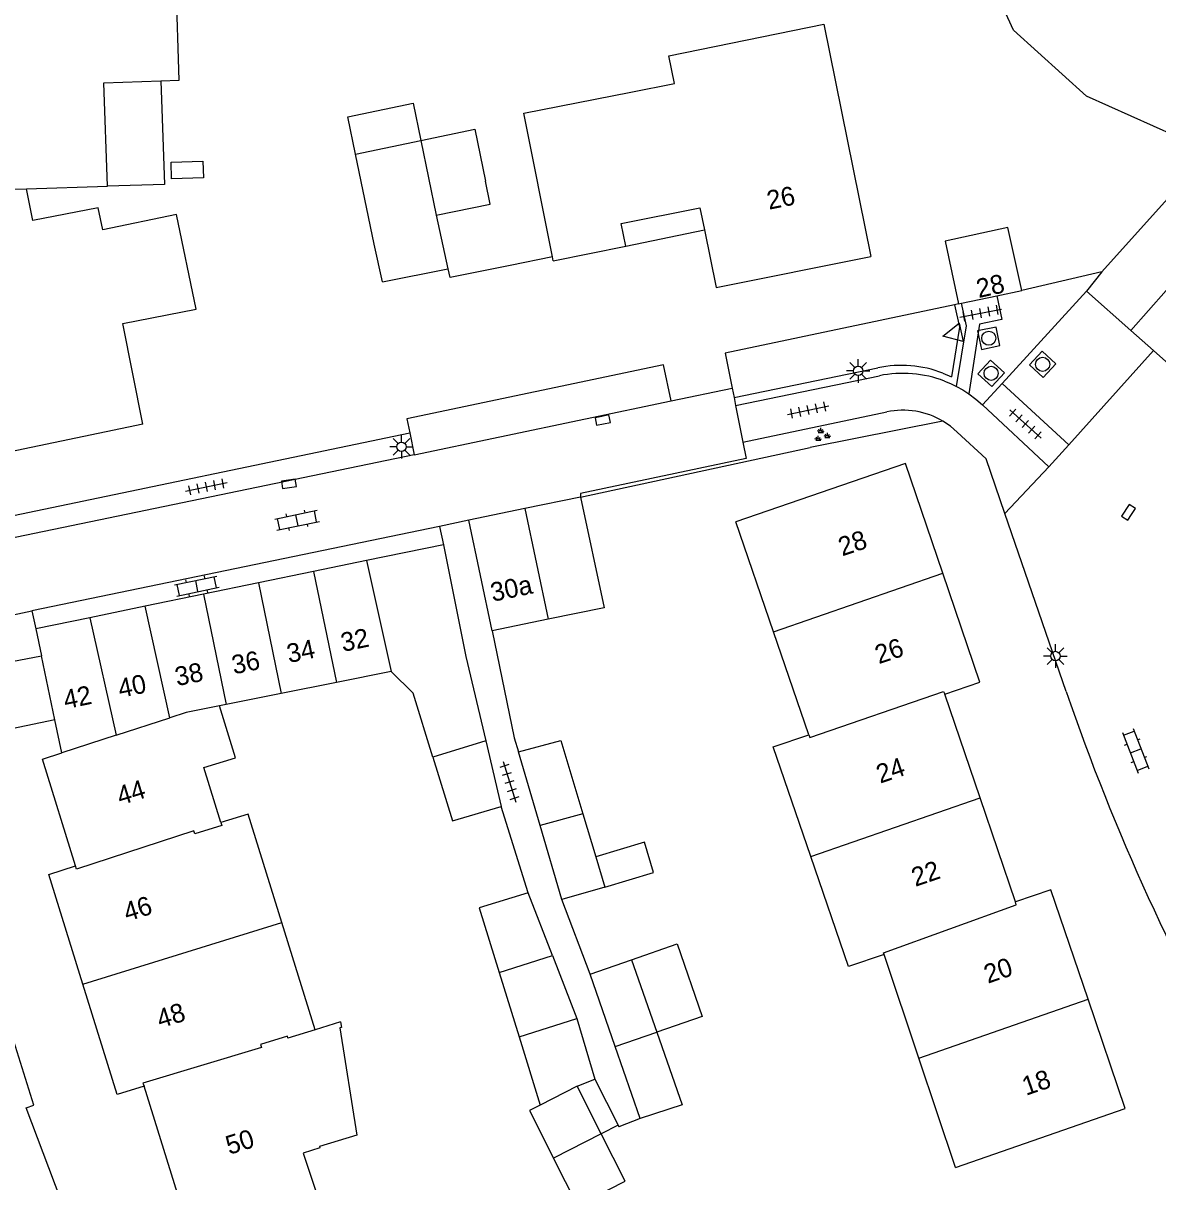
# Model space of a CAD drawing. Extents: x 126000 to 131009, y 393000 to 395500.
# Drawn here: x 130394.9 to 130455.1, y 394946.8 to 395008.4 of the extents above; entities that cross this region are included whole.
import ezdxf

# ---------------------------------------------------------------- set-up
doc = ezdxf.new("R2010")
doc.units = 0
for name, color, linetype in [('gg-afsc-erfafscheiding', 7, 'Continuous'), ('gg-afsc-muur', 7, 'Continuous'), ('gg-anno-huisnummerreeks BGT', 7, 'Continuous'), ('gg-bbg-bijgebouw', 7, 'Continuous'), ('gg-bbg-gedigitaliseerde bebouwing', 7, 'Continuous'), ('gg-bbg-gedigitaliseerde bijgebouw', 7, 'Continuous'), ('gg-bbg-hoofdgebouw', 7, 'Continuous'), ('gg-bbg-luifel en loopbrug', 7, 'Continuous'), ('gg-bbg-tussenscheiding', 7, 'Continuous'), ('gg-knt-verharding', 7, 'Continuous'), ('gg-knt-verharding nz', 7, 'Continuous'), ('gg-kntw-beschoeiing', 7, 'Continuous'), ('gt-grn-groengrens', 7, 'Continuous'), ('gt-symb-groenvak', 7, 'Continuous'), ('gt-symb-klinker verharding', 7, 'Continuous'), ('gt-symb-kolk', 7, 'Continuous'), ('gt-symb-lichtmast', 7, 'Continuous'), ('gt-symb-rioolschacht', 7, 'Continuous'), ('gt-symb-tegel verharding', 7, 'Continuous'), ('gt-symb-waterafsluiter', 7, 'Continuous')]:
    doc.layers.add(name, color=color, linetype=linetype)

# ---------------------------------------------------------------- blocks, each defined once
blk = doc.blocks.new('gt0-KL1')
at = {"layer": 'gt-symb-klinker verharding'}
for p, q in [((-1.15, 0.3), (1.15, 0.3)), ((-1, -0.3), (-1, 0.3)), ((-0.5, 0.3), (-0.5, 0.45)), ((0, -0.3), (0, 0.3)), ((0.5, 0.3), (0.5, 0.45)), ((1, -0.3), (1, 0.3)), ((-1.15, -0.3), (1.15, -0.3)), ((-0.5, -0.45), (-0.5, -0.3)), ((0.5, -0.45), (0.5, -0.3))]:
    blk.add_line(p, q, dxfattribs=at)
blk = doc.blocks.new('gt0-TEG1')
at = {"layer": 'gt-symb-tegel verharding'}
for p, q in [((-1.125, 0), (1.125, 0)), ((-0.9, -0.25), (-0.9, 0.25)), ((-0.45, -0.25), (-0.45, 0.25)), ((0, -0.25), (0, 0.25)), ((0.45, -0.25), (0.45, 0.25)), ((0.9, -0.25), (0.9, 0.25))]:
    blk.add_line(p, q, dxfattribs=at)
blk = doc.blocks.new('gt0-GRVAK')
at = {"layer": 'gt-symb-groenvak'}
for p, q in [((-0.11, 0.189), (-0.228, 0.24)), ((-0.182, 0.153), (0.088, 0.153)), ((-0.091, 0.211), (-0.156, 0.322)), ((-0.047, 0.214), (-0.047, 0.393)), ((-0.004, 0.211), (0.061, 0.322)), ((0.015, 0.189), (0.133, 0.24)), ((0.262, -0.052), (0.197, 0.059)), ((0.305, -0.049), (0.305, 0.13)), ((0.349, -0.052), (0.414, 0.059)), ((-0.245, -0.228), (-0.363, -0.177)), ((-0.318, -0.264), (-0.047, -0.264)), ((-0.226, -0.206), (-0.291, -0.095)), ((-0.183, -0.203), (-0.183, -0.024)), ((-0.139, -0.206), (-0.074, -0.095)), ((-0.12, -0.228), (-0.002, -0.177)), ((0.243, -0.074), (0.125, -0.023)), ((0.17, -0.11), (0.441, -0.11)), ((0.368, -0.074), (0.486, -0.023))]:
    blk.add_line(p, q, dxfattribs=at)
blk = doc.blocks.new('gt0-KOLK')
at = {"layer": 'gt-symb-kolk'}
blk.add_lwpolyline([(0, 0), (0.375, 0), (0.375, 0.4), (-0.375, 0.4), (-0.375, 0), (0, 0)], dxfattribs=at)
blk = doc.blocks.new('gt0-RS')
at = {"layer": 'gt-symb-rioolschacht'}
blk.add_lwpolyline([(-0.5, -0.5), (0.5, -0.5), (0.5, 0.5), (-0.5, 0.5)], close=True, dxfattribs=at)
blk.add_circle((0, 0), 0.375, dxfattribs=at)
blk = doc.blocks.new('gt0-LMAST')
at = {"layer": 'gt-symb-lichtmast'}
for p, q in [((-0.005, 0.246), (-0.005, 0.621)), ((-0.182, 0.173), (-0.447, 0.438)), ((0.172, 0.173), (0.437, 0.438)), ((-0.255, -0.004), (-0.63, -0.004)), ((-0.182, -0.181), (-0.447, -0.446)), ((-0.005, -0.254), (-0.005, -0.629)), ((0.437, -0.446), (0.172, -0.181)), ((0.245, -0.004), (0.62, -0.004))]:
    blk.add_line(p, q, dxfattribs=at)
blk.add_circle((-0.005, -0.004), 0.25, dxfattribs=at)
blk = doc.blocks.new('gt0-WAFSL')
at = {"layer": 'gt-symb-waterafsluiter'}
for p, q in [((-0.5, -0.333), (0, 0.667)), ((0, 0.667), (0.5, -0.333)), ((0.5, -0.333), (-0.5, -0.333))]:
    blk.add_line(p, q, dxfattribs=at)

msp = doc.modelspace()

# ---------------------------------------------------------------- linework, layer by layer
at = {"layer": 'gg-afsc-erfafscheiding'}
for p, q in [((130422.965, 394995.976), (130420.721, 394995.525)), ((130424.46, 394983.224), (130436.661, 394985.85)), ((130416.969, 394981.665), (130417.172, 394980.691)), ((130421.68, 394962.2), (130420.25, 394966.79)), ((130424.97, 394957.88), (130423.47, 394961.84)), ((130427.63, 394950.2), (130426.495, 394949.763)), ((130426.448, 394949.856), (130426.495, 394949.763))]:
    msp.add_line(p, q, dxfattribs=at)
msp.add_lwpolyline([(130419.77, 394976.122), (130420.94, 394970.437), (130421.16, 394969.69)], dxfattribs=at)
at = {"layer": 'gg-afsc-muur'}
msp.add_lwpolyline([(130420.721, 394995.525), (130417.525, 394994.883), (130417.43, 394995.353), (130417.401, 394995.347)], dxfattribs=at)
at = {"layer": 'gg-bbg-bijgebouw'}
for p, q in [((130413.943, 394994.646), (130417.401, 394995.347)), ((130424.46, 394983.224), (130421.495, 394982.607)), ((130417.172, 394980.691), (130413.088, 394979.847)), ((130413.088, 394979.847), (130410.282, 394979.267)), ((130410.282, 394979.267), (130407.358, 394978.663)), ((130407.358, 394978.663), (130404.434, 394978.059)), ((130404.434, 394978.059), (130401.327, 394977.417)), ((130401.327, 394977.417), (130398.389, 394976.81)), ((130398.389, 394976.81), (130395.527, 394976.219)), ((130395.527, 394976.219), (130395.824, 394974.794)), ((130396.535, 394971.381), (130395.824, 394974.794)), ((130396.9, 394969.632), (130396.535, 394971.381))]:
    msp.add_line(p, q, dxfattribs=at)
at = {"layer": 'gg-bbg-gedigitaliseerde bebouwing'}
for p, q in [((130437.38, 395008.35), (130439.874, 394996.006)), ((130395.04, 394999.6), (130399.33, 394999.73)), ((130401.218, 394987.088), (130400.15, 394992.44)), ((130419.77, 394976.122), (130418.53, 394981.989)), ((130434.712, 394976.054), (130432.711, 394981.906)), ((130422.745, 394976.731), (130419.77, 394976.122)), ((130436.58, 394970.59), (130434.712, 394976.054)), ((130410.357, 394954.927), (130408.586, 394960.627)), ((130442.428, 394953.419), (130440.58, 394958.92)), ((130411.713, 394955.349), (130410.357, 394954.927)), ((130444.38, 394947.61), (130442.428, 394953.419)), ((130444.38, 394947.61), (130453.389, 394950.744))]:
    msp.add_line(p, q, dxfattribs=at)
for points in [[(130402.168, 395005.326), (130403.14, 395005.36), (130402.98, 395010.45), (130402.382, 395010.428)], [(130421.437, 395003.614), (130427.13, 395004.723), (130429.45, 395005.19), (130429.15, 395006.66), (130437.38, 395008.35)], [(130399.33, 394999.73), (130399.14, 395005.22), (130402.168, 395005.326)], [(130400.15, 394992.44), (130404.04, 394993.21), (130403, 394998.23), (130399.08, 394997.41), (130398.83, 394998.59), (130395.37, 394997.92), (130395.04, 394999.6)], [(130405.351, 394965.935), (130404.45, 394968.854), (130406.132, 394969.374), (130405.28, 394972.134)], [(130436.683, 394964.121), (130434.69, 394969.95), (130436.58, 394970.59)], [(130408.586, 394960.627), (130406.798, 394966.384), (130405.351, 394965.935)], [(130440.58, 394958.92), (130438.68, 394958.28), (130436.683, 394964.121)]]:
    msp.add_lwpolyline(points, dxfattribs=at)
at = {"layer": 'gg-bbg-gedigitaliseerde bijgebouw'}
for p, q in [((130416.798, 394998.197), (130417.401, 394995.347)), ((130417.172, 394980.691), (130418.361, 394974.753)), ((130418.361, 394974.753), (130419.425, 394970.269)), ((130414.4, 394973.96), (130411.492, 394973.378)), ((130408.561, 394972.791), (130405.633, 394972.205)), ((130411.492, 394973.378), (130408.561, 394972.791)), ((130405.633, 394972.205), (130405.28, 394972.134)), ((130419.425, 394970.269), (130420.25, 394966.79)), ((130422.314, 394965.768), (130421.16, 394969.69)), ((130424.579, 394966.4), (130425.266, 394964.111)), ((130423.47, 394961.84), (130422.314, 394965.768)), ((130425.266, 394964.111), (130425.75, 394962.5)), ((130425.75, 394962.5), (130423.47, 394961.84)), ((130422.97, 394958.86), (130421.68, 394962.2)), ((130422.97, 394958.86), (130424.26, 394955.52)), ((130424.97, 394957.88), (130427.16, 394958.64)), ((130427.16, 394958.64), (130428.504, 394954.793)), ((130420.135, 394957.969), (130421.19, 394954.54)), ((130426.301, 394954.038), (130424.97, 394957.88)), ((130421.19, 394954.54), (130424.26, 394955.52)), ((130427.63, 394950.2), (130426.301, 394954.038)), ((130424.28, 394951.92), (130422.305, 394950.917)), ((130425.554, 394949.401), (130424.28, 394951.92)), ((130424.3, 394945.59), (130423.02, 394948.11))]:
    msp.add_line(p, q, dxfattribs=at)
for points in [[(130412.51, 395001.44), (130412.098, 395003.427), (130415.573, 395004.148), (130415.98, 395002.17)], [(130415.98, 395002.17), (130418.847, 395002.76), (130419.415, 395000)], [(130413.943, 394994.646), (130413.503, 394996.656), (130412.51, 395001.44)], [(130416.798, 394998.197), (130419.665, 394998.787), (130419.415, 395000)], [(130424.46, 394983.224), (130425.72, 394977.34), (130422.745, 394976.731)], [(130416.612, 394969.41), (130415.56, 394972.8), (130414.4, 394973.96)], [(130421.16, 394969.69), (130423.41, 394970.29), (130424.579, 394966.4)], [(130416.612, 394969.41), (130417.66, 394966.03), (130420.25, 394966.79)], [(130421.68, 394962.2), (130419.08, 394961.4), (130420.135, 394957.969)], [(130428.504, 394954.793), (130429.85, 394950.94), (130427.63, 394950.2)], [(130422.305, 394950.917), (130421.74, 394950.63), (130423.02, 394948.11)], [(130424.3, 394945.59), (130426.83, 394946.88), (130425.554, 394949.401)]]:
    msp.add_lwpolyline(points, dxfattribs=at)
at = {"layer": 'gg-bbg-hoofdgebouw'}
for p, q in [((130422.965, 394995.976), (130421.437, 395003.614)), ((130423.005, 394995.777), (130426.858, 394996.552)), ((130423.005, 394995.777), (130422.965, 394995.976)), ((130444.695, 394993.514), (130446.562, 394993.909)), ((130446.562, 394993.909), (130447.891, 394994.19)), ((130444.524, 394993.478), (130444.695, 394993.514)), ((130421.495, 394982.607), (130418.53, 394981.989)), ((130445.675, 394967.235), (130443.796, 394972.748)), ((130447.555, 394961.716), (130445.675, 394967.235)), ((130453.389, 394950.744), (130451.41, 394956.554))]:
    msp.add_line(p, q, dxfattribs=at)
for points in [[(130426.858, 394996.552), (130426.615, 394997.76), (130430.795, 394998.593), (130431.036, 394997.416)], [(130431.036, 394997.416), (130431.666, 394994.347), (130439.874, 394996.006)], [(130447.891, 394994.19), (130447.142, 394997.548), (130443.82, 394996.807), (130444.524, 394993.478)], [(130401.218, 394987.088), (130393.315, 394985.453), (130392.237, 394990.549), (130390.919, 394990.27)], [(130443.697, 394979.186), (130441.724, 394984.999), (130432.711, 394981.906)], [(130443.796, 394972.748), (130445.667, 394973.383), (130443.697, 394979.186)], [(130397.632, 394963.627), (130395.88, 394969.304), (130396.9, 394969.632)], [(130398.031, 394957.336), (130396.216, 394963.178), (130397.632, 394963.627)], [(130451.41, 394956.554), (130449.436, 394962.351), (130447.555, 394961.716)], [(130401.273, 394951.933), (130399.847, 394951.49), (130398.031, 394957.336)], [(130411.713, 394955.349), (130411.758, 394955.035), (130411.677, 394955.019), (130412.57, 394949.322), (130410.6, 394948.716), (130410.619, 394948.654), (130409.724, 394948.365), (130410.436, 394946.239), (130403.063, 394943.186)], [(130402.157, 394945.922), (130403.056, 394946.227), (130401.273, 394951.933)]]:
    msp.add_lwpolyline(points, dxfattribs=at)
at = {"layer": 'gg-bbg-luifel en loopbrug'}
for p, q in [((130426.858, 394996.552), (130431.036, 394997.416)), ((130424.26, 394955.52), (130425.21, 394952.303)), ((130421.19, 394954.54), (130422.305, 394950.917)), ((130424.28, 394951.92), (130425.21, 394952.303)), ((130425.21, 394952.303), (130426.448, 394949.856)), ((130426.448, 394949.856), (130425.554, 394949.401))]:
    msp.add_line(p, q, dxfattribs=at)
for points in [[(130402.168, 395005.326), (130402.359, 394999.818), (130399.33, 394999.73)], [(130402.74, 395000.118), (130402.709, 395001.014), (130404.396, 395001.073), (130404.427, 395000.176), (130402.74, 395000.118)], [(130425.75, 394962.5), (130428.339, 394963.277), (130427.856, 394964.888), (130425.266, 394964.111)], [(130427.16, 394958.64), (130429.582, 394959.48), (130430.921, 394955.621), (130428.504, 394954.793)]]:
    msp.add_lwpolyline(points, dxfattribs=at)
at = {"layer": 'gg-bbg-tussenscheiding'}
for p, q in [((130412.51, 395001.44), (130415.98, 395002.17)), ((130415.98, 395002.17), (130416.798, 394998.197)), ((130392.042, 394999.511), (130395.04, 394999.6)), ((130421.495, 394982.607), (130422.745, 394976.731)), ((130413.088, 394979.847), (130414.4, 394973.96)), ((130410.282, 394979.267), (130411.492, 394973.378)), ((130434.712, 394976.054), (130443.697, 394979.186)), ((130407.358, 394978.663), (130408.561, 394972.791)), ((130404.434, 394978.059), (130405.633, 394972.205)), ((130402.65, 394971.5), (130401.327, 394977.417)), ((130398.389, 394976.81), (130399.79, 394970.57)), ((130399.79, 394970.57), (130402.65, 394971.5)), ((130399.79, 394970.57), (130396.9, 394969.632)), ((130419.425, 394970.269), (130416.612, 394969.41)), ((130436.683, 394964.121), (130445.675, 394967.235)), ((130424.579, 394966.4), (130422.314, 394965.768)), ((130398.031, 394957.336), (130408.586, 394960.627)), ((130420.135, 394957.969), (130422.97, 394958.86)), ((130442.428, 394953.419), (130451.41, 394956.554)), ((130426.301, 394954.038), (130428.504, 394954.793)), ((130425.554, 394949.401), (130423.02, 394948.11))]:
    msp.add_line(p, q, dxfattribs=at)
for points in [[(130436.58, 394970.59), (130436.64, 394970.44), (130443.73, 394972.89), (130443.796, 394972.748)], [(130405.28, 394972.134), (130403.51, 394971.78), (130402.65, 394971.5)], [(130405.351, 394965.935), (130405.4, 394965.78), (130403.97, 394965.33), (130403.92, 394965.49), (130397.69, 394963.46), (130397.632, 394963.627)], [(130440.58, 394958.92), (130440.54, 394959.01), (130447.6, 394961.56), (130447.555, 394961.716)], [(130410.357, 394954.927), (130408.92, 394954.48), (130408.89, 394954.58), (130407.46, 394954.14), (130407.51, 394953.98), (130401.21, 394952.08), (130401.273, 394951.933)]]:
    msp.add_lwpolyline(points, dxfattribs=at)
at = {"layer": 'gg-knt-verharding'}
for p, q in [((130446.854, 394989.252), (130451.32, 394994.155)), ((130451.32, 394994.155), (130453.677, 394992.067)), ((130453.677, 394992.067), (130454.882, 394991)), ((130454.882, 394991), (130457.015, 394989.111)), ((130432.692, 394988.094), (130440.331, 394989.666)), ((130429.271, 394988.329), (130432.511, 394989.007)), ((130432.511, 394989.007), (130432.608, 394988.517)), ((130446.854, 394989.252), (130445.811, 394988.116)), ((130450.383, 394986.003), (130446.854, 394989.252)), ((130415.63, 394985.473), (130429.271, 394988.329)), ((130432.608, 394988.517), (130432.692, 394988.094)), ((130432.692, 394988.094), (130433.08, 394986.143)), ((130433.08, 394986.143), (130440.722, 394987.747)), ((130445.811, 394988.116), (130449.324, 394984.827)), ((130392.975, 394981.953), (130415.384, 394986.634)), ((130415.384, 394986.634), (130415.63, 394985.473)), ((130449.324, 394984.827), (130450.383, 394986.003)), ((130415.63, 394985.473), (130391.557, 394980.488)), ((130449.324, 394984.827), (130446.996, 394982.343)), ((130450.249, 394972.887), (130446.996, 394982.343)), ((130416.969, 394981.665), (130395.318, 394977.178)), ((130418.53, 394981.989), (130416.969, 394981.665)), ((130390.711, 394976.212), (130395.318, 394977.178)), ((130395.318, 394977.178), (130395.527, 394976.219)), ((130389.238, 394973.522), (130395.824, 394974.794))]:
    msp.add_line(p, q, dxfattribs=at)
for points in [[(130446.562, 394993.909), (130446.826, 394992.659), (130445.651, 394992.412), (130445.075, 394988.708)], [(130444.429, 394989.096), (130444.948, 394992.32), (130444.695, 394993.514)], [(130429.271, 394988.329), (130428.872, 394990.237), (130415.226, 394987.381), (130415.384, 394986.634)], [(130443.79, 394989.384), (130444.114, 394989.249), (130444.429, 394989.096)], [(130444.429, 394989.096), (130444.756, 394988.913), (130445.075, 394988.708)], [(130445.075, 394988.708), (130445.455, 394988.426), (130445.811, 394988.116)], [(130446.996, 394982.343), (130445.995, 394985.252), (130444.464, 394986.673), (130444.099, 394986.986), (130443.701, 394987.254)], [(130433.08, 394986.143), (130433.255, 394985.261), (130424.449, 394983.409), (130424.46, 394983.224)], [(130400.844, 394936.262), (130397.779, 394943.457), (130395.019, 394950.775), (130395.417, 394950.912), (130392.754, 394959.414), (130391.222, 394965.211), (130390.069, 394970.041)]]:
    msp.add_lwpolyline(points, dxfattribs=at)
for centre, radius, start, end in [((130441.579, 394983.613), 6.18, 69.03295, 101.64542), ((130441.579, 394983.679), 4.157, 59.30819, 101.89818), ((130565.002, 395012.359), 121.352, 198.98191, 221.18932), ((130537.726, 395000.202), 153.532, 198.50282, 204.93954)]:
    msp.add_arc(centre, radius, start, end, dxfattribs=at)
at = {"layer": 'gg-knt-verharding nz'}
msp.add_line((130450.383, 394986.003), (130454.882, 394991), dxfattribs=at)
at = {"layer": 'gg-kntw-beschoeiing'}
msp.add_lwpolyline([(130458.891, 395002.691), (130456.071, 395002.4), (130451.331, 395004.515), (130447.458, 395008.022), (130445.383, 395012.561), (130445.209, 395016.983), (130446.693, 395021.735)], dxfattribs=at)
at = {"layer": 'gt-grn-groengrens'}
for p, q in [((130455.635, 394999.064), (130452.145, 394995.178)), ((130453.677, 394992.067), (130459.9, 394999.113)), ((130452.145, 394995.178), (130447.891, 394994.19)), ((130452.145, 394995.178), (130451.32, 394994.155)), ((130444.524, 394993.478), (130444.322, 394993.435)), ((130432.608, 394988.517), (130440.244, 394990.089)), ((130443.703, 394989.807), (130444.152, 394989.613)), ((130443.701, 394987.254), (130436.661, 394985.85)), ((130396.535, 394971.381), (130390.069, 394970.041))]:
    msp.add_line(p, q, dxfattribs=at)
for points in [[(130444.322, 394993.435), (130432.144, 394990.86), (130432.511, 394989.007)], [(130444.322, 394993.435), (130444.575, 394992.241), (130444.152, 394989.613)]]:
    msp.add_lwpolyline(points, dxfattribs=at)
msp.add_arc((130441.49, 394984.019), 6.196, 69.07644, 101.60193, dxfattribs=at)

# ---------------------------------------------------------------- block references
at = {"layer": 'gt-symb-groenvak'}
msp.add_blockref('gt0-GRVAK', (130437.264, 394986.499), dxfattribs=at)
at = {"layer": 'gt-symb-klinker verharding'}
for p, rotation in [((130409.401, 394981.989), 11.71452521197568), ((130404.079, 394978.492), 11.71452521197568), ((130453.94, 394969.743), -68.95425918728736)]:
    msp.add_blockref('gt0-KL1', p, dxfattribs=dict(at, rotation=rotation))
at = {"layer": 'gt-symb-kolk'}
for p, rotation in [((130425.593, 394987.504), -167.993291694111), ((130408.939, 394984.119), -171.37577126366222), ((130453.72, 394982.301), 57.24756054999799)]:
    msp.add_blockref('gt0-KOLK', p, dxfattribs=dict(at, rotation=rotation))
at = {"layer": 'gt-symb-lichtmast'}
for p in [(130439.209, 394989.925), (130414.953, 394985.896), (130449.683, 394974.781)]:
    msp.add_blockref('gt0-LMAST', p, dxfattribs=at)
at = {"layer": 'gt-symb-rioolschacht'}
for p, rotation in [((130446.139, 394991.66), 101.95064726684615), ((130449, 394990.272), 47.67618346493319), ((130446.265, 394989.794), 47.67618346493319)]:
    msp.add_blockref('gt0-RS', p, dxfattribs=dict(at, rotation=rotation))
at = {"layer": 'gt-symb-tegel verharding'}
for p, rotation in [((130445.708, 394992.991), 11.00666417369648), ((130436.55, 394987.845), 11.826703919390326), ((130448.081, 394987.103), -42.323816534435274), ((130404.586, 394983.763), 11.71452520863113), ((130420.687, 394968.092), -72.85095611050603)]:
    msp.add_blockref('gt0-TEG1', p, dxfattribs=dict(at, rotation=rotation))
at = {"layer": 'gt-symb-waterafsluiter', "rotation": 101.95064726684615}
msp.add_blockref('gt0-WAFSL', (130444.345, 394991.907), dxfattribs=at)

# ---------------------------------------------------------------- texts
at = {"layer": 'gg-anno-huisnummerreeks BGT'}
for s, rotation, p in [('26', 11.4, (130434.464, 394998.483)), ('28', 12.6, (130445.6, 394993.789)), ('28', 18.7, (130438.354, 394980.067)), ('30a', 11.8, (130419.79, 394977.655)), ('32', 11.7, (130411.835, 394974.992)), ('34', 11.7, (130408.969, 394974.4)), ('26', 18.7, (130440.298, 394974.338)), ('36', 11.7, (130406.045, 394973.796)), ('38', 11.7, (130403.03, 394973.173)), ('40', 11.7, (130400.007, 394972.548)), ('42', 11.7, (130397.107, 394971.949)), ('24', 18.8, (130440.37, 394967.995)), ('44', 17.1, (130400.014, 394966.837)), ('22', 18.8, (130442.238, 394962.511)), ('46', 17.3, (130400.372, 394960.662)), ('20', 18.8, (130446.088, 394957.366)), ('48', 17.3, (130402.134, 394954.99)), ('18', 18.8, (130448.115, 394951.413)), ('50', 17.4, (130405.797, 394948.272))]:
    msp.add_text(s, height=1, rotation=rotation, dxfattribs=at).set_placement(p)

doc.saveas('drawing.dxf')
